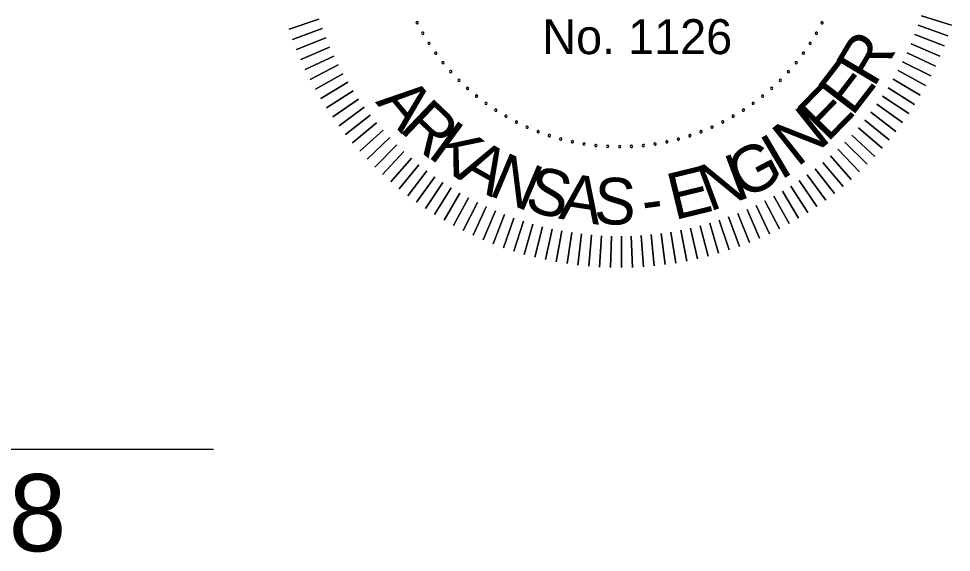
# Model space of a CAD drawing. Extents: x 164 to 3385, y 68 to 2119.
# Drawn here: x 2632.5 to 2965.9, y 339.7 to 530.6 of the extents above; entities that cross this region are included whole.
import ezdxf

# ---------------------------------------------------------------- set-up
doc = ezdxf.new("R2010")
doc.units = 0
doc.layers.add('G-ANNO-TEXT', color=7, linetype='Continuous')
doc.layers.add('R_Annotation', color=7, linetype='Continuous')

msp = doc.modelspace()

# ---------------------------------------------------------------- linework, layer by layer
at = {"layer": 'G-ANNO-TEXT'}
for points in [[(2739.82, 530.37), (2729.17, 526.84)], [(2729.17, 526.84), (2739.82, 530.37)], [(2965.87, 528.16), (2955.18, 531.57)], [(2955.18, 531.57), (2965.87, 528.16)], [(2740.99, 527.01), (2730.46, 523.15)], [(2730.46, 523.15), (2740.99, 527.01)], [(2964.62, 524.45), (2954.04, 528.19)], [(2954.04, 528.19), (2964.62, 524.45)], [(2742.27, 523.69), (2731.86, 519.5)], [(2731.86, 519.5), (2742.27, 523.69)], [(2963.26, 520.79), (2952.8, 524.86)], [(2952.8, 524.86), (2963.26, 520.79)], [(2743.65, 520.41), (2733.38, 515.89)], [(2733.38, 515.89), (2743.65, 520.41)], [(2961.79, 517.17), (2951.46, 521.57)], [(2951.46, 521.57), (2961.79, 517.17)], [(2745.13, 517.18), (2735, 512.34)], [(2735, 512.34), (2745.13, 517.18)], [(2960.2, 513.6), (2950.02, 518.32)], [(2950.02, 518.32), (2960.2, 513.6)], [(2746.71, 513.99), (2736.74, 508.84)], [(2736.74, 508.84), (2746.71, 513.99)], [(2958.5, 510.08), (2948.47, 515.11)], [(2948.47, 515.11), (2958.5, 510.08)], [(2748.4, 510.86), (2738.59, 505.39)], [(2738.59, 505.39), (2748.4, 510.86)], [(2956.69, 506.61), (2946.82, 511.96)], [(2946.82, 511.96), (2956.69, 506.61)], [(2750.18, 507.78), (2740.55, 502.01)], [(2740.55, 502.01), (2750.18, 507.78)], [(2954.77, 503.2), (2945.08, 508.86)], [(2945.08, 508.86), (2954.77, 503.2)], [(2752.05, 504.75), (2742.61, 498.69)], [(2742.61, 498.69), (2752.05, 504.75)], [(2952.74, 499.86), (2943.24, 505.82)], [(2943.24, 505.82), (2952.74, 499.86)], [(2754.02, 501.79), (2744.77, 495.43)], [(2744.77, 495.43), (2754.02, 501.79)], [(2950.62, 496.58), (2941.3, 502.84)], [(2941.3, 502.84), (2950.62, 496.58)], [(2756.08, 498.89), (2747.04, 492.25)], [(2747.04, 492.25), (2756.08, 498.89)], [(2946.06, 490.23), (2937.15, 497.06)], [(2937.15, 497.06), (2946.06, 490.23)], [(2948.39, 493.37), (2939.27, 499.91)], [(2939.27, 499.91), (2948.39, 493.37)], [(2758.23, 496.06), (2749.4, 489.13)], [(2749.4, 489.13), (2758.23, 496.06)], [(2943.63, 487.17), (2934.94, 494.27)], [(2934.94, 494.27), (2943.63, 487.17)], [(2760.47, 493.3), (2751.86, 486.1)], [(2751.86, 486.1), (2760.47, 493.3)], [(2762.8, 490.61), (2754.42, 483.14)], [(2754.42, 483.14), (2762.8, 490.61)], [(2941.11, 484.18), (2932.65, 491.55)], [(2932.65, 491.55), (2941.11, 484.18)], [(2765.21, 487.99), (2757.07, 480.26)], [(2757.07, 480.26), (2765.21, 487.99)], [(2938.49, 481.27), (2930.27, 488.91)], [(2930.27, 488.91), (2938.49, 481.27)], [(2767.69, 485.45), (2759.8, 477.47)], [(2759.8, 477.47), (2767.69, 485.45)], [(2932.99, 475.71), (2925.27, 483.85)], [(2925.27, 483.85), (2932.99, 475.71)], [(2935.79, 478.45), (2927.81, 486.34)], [(2927.81, 486.34), (2935.79, 478.45)], [(2770.26, 482.99), (2762.63, 474.76)], [(2762.63, 474.76), (2770.26, 482.99)], [(2765.53, 472.15), (2772.91, 480.61)], [(2772.91, 480.61), (2765.53, 472.15)], [(2930.12, 473.07), (2922.65, 481.44)], [(2922.65, 481.44), (2930.12, 473.07)], [(2768.52, 469.63), (2775.62, 478.31)], [(2775.62, 478.31), (2768.52, 469.63)], [(2924.12, 468.05), (2917.19, 476.88)], [(2917.19, 476.88), (2924.12, 468.05)], [(2927.16, 470.51), (2919.96, 479.12)], [(2919.96, 479.12), (2927.16, 470.51)], [(2771.58, 467.2), (2778.41, 476.11)], [(2778.41, 476.11), (2771.58, 467.2)], [(2774.72, 464.87), (2781.27, 473.99)], [(2781.27, 473.99), (2774.72, 464.87)], [(2921.01, 465.69), (2914.36, 474.73)], [(2914.36, 474.73), (2921.01, 465.69)], [(2777.93, 462.64), (2784.19, 471.96)], [(2784.19, 471.96), (2777.93, 462.64)], [(2781.21, 460.51), (2787.17, 470.02)], [(2787.17, 470.02), (2781.21, 460.51)], [(2914.57, 461.26), (2908.5, 470.7)], [(2908.5, 470.7), (2914.57, 461.26)], [(2917.82, 463.42), (2911.46, 472.67)], [(2911.46, 472.67), (2917.82, 463.42)], [(2784.56, 458.49), (2790.22, 468.18)], [(2790.22, 468.18), (2784.56, 458.49)], [(2907.86, 457.24), (2902.4, 467.04)], [(2902.4, 467.04), (2907.86, 457.24)], [(2911.25, 459.19), (2905.48, 468.82)], [(2905.48, 468.82), (2911.25, 459.19)], [(2787.96, 456.57), (2793.32, 466.43)], [(2793.32, 466.43), (2787.96, 456.57)], [(2791.43, 454.76), (2796.47, 464.79)], [(2796.47, 464.79), (2791.43, 454.76)], [(2900.92, 453.65), (2896.08, 463.78)], [(2896.08, 463.78), (2900.92, 453.65)], [(2904.42, 455.39), (2899.27, 465.36)], [(2899.27, 465.36), (2904.42, 455.39)], [(2794.95, 453.06), (2799.67, 463.24)], [(2799.67, 463.24), (2794.95, 453.06)], [(2798.52, 451.47), (2802.92, 461.8)], [(2802.92, 461.8), (2798.52, 451.47)], [(2802.14, 450), (2806.21, 460.45)], [(2806.21, 460.45), (2802.14, 450)], [(2893.76, 450.51), (2889.57, 460.92)], [(2889.57, 460.92), (2893.76, 450.51)], [(2897.36, 452.02), (2892.85, 462.3)], [(2892.85, 462.3), (2897.36, 452.02)], [(2805.81, 448.63), (2809.55, 459.21)], [(2809.55, 459.21), (2805.81, 448.63)], [(2809.51, 447.39), (2812.92, 458.08)], [(2812.92, 458.08), (2809.51, 447.39)], [(2813.25, 446.26), (2816.32, 457.05)], [(2816.32, 457.05), (2813.25, 446.26)], [(2882.69, 446.65), (2879.5, 457.41)], [(2879.5, 457.41), (2882.69, 446.65)], [(2886.42, 447.82), (2882.89, 458.47)], [(2882.89, 458.47), (2886.42, 447.82)], [(2890.11, 449.1), (2886.25, 459.64)], [(2886.25, 459.64), (2890.11, 449.1)], [(2817.03, 445.25), (2819.76, 456.13)], [(2819.76, 456.13), (2817.03, 445.25)], [(2820.84, 444.36), (2823.22, 455.32)], [(2823.22, 455.32), (2820.84, 444.36)], [(2824.67, 443.59), (2826.71, 454.62)], [(2826.71, 454.62), (2824.67, 443.59)], [(2828.52, 442.94), (2830.22, 454.03)], [(2830.22, 454.03), (2828.52, 442.94)], [(2832.4, 442.41), (2833.74, 453.55)], [(2833.74, 453.55), (2832.4, 442.41)], [(2863.59, 442.58), (2862.12, 453.71)], [(2862.12, 453.71), (2863.59, 442.58)], [(2867.46, 443.15), (2865.64, 454.23)], [(2865.64, 454.23), (2867.46, 443.15)], [(2871.3, 443.85), (2869.14, 454.86)], [(2869.14, 454.86), (2871.3, 443.85)], [(2875.13, 444.66), (2872.62, 455.6)], [(2872.62, 455.6), (2875.13, 444.66)], [(2878.92, 445.59), (2876.07, 456.45)], [(2876.07, 456.45), (2878.92, 445.59)], [(2836.28, 442), (2837.28, 453.18)], [(2837.28, 453.18), (2836.28, 442)], [(2840.18, 441.71), (2840.83, 452.92)], [(2840.83, 452.92), (2840.18, 441.71)], [(2844.09, 441.55), (2844.38, 452.77)], [(2844.38, 452.77), (2844.09, 441.55)], [(2848, 441.51), (2847.94, 452.73)], [(2847.94, 452.73), (2848, 441.51)], [(2851.91, 441.6), (2851.49, 452.81)], [(2851.49, 452.81), (2851.91, 441.6)], [(2855.81, 441.8), (2855.04, 453)], [(2855.04, 453), (2855.81, 441.8)], [(2859.71, 442.13), (2858.59, 453.3)], [(2858.59, 453.3), (2859.71, 442.13)]]:
    msp.add_lwpolyline(points, dxfattribs=at)
for centre, start, end in [((2774.94, 529.08), 117, 297), ((2774.94, 529.08), 297, 117), ((2919.67, 529.08), 63, 243), ((2919.67, 529.08), 243, 63), ((2776.97, 525.34), 120, 300), ((2776.97, 525.34), 300, 120), ((2917.64, 525.34), 60, 240), ((2917.64, 525.34), 240, 60), ((2779.19, 521.72), 123, 303), ((2779.19, 521.72), 303, 123), ((2915.42, 521.72), 57, 237), ((2915.42, 521.72), 237, 57), ((2781.6, 518.21), 126, 306), ((2781.6, 518.21), 306, 126), ((2913.01, 518.21), 54, 234), ((2913.01, 518.21), 234, 54), ((2784.19, 514.84), 129, 309), ((2784.19, 514.84), 309, 129), ((2910.42, 514.84), 51, 231), ((2910.42, 514.84), 231, 51), ((2786.95, 511.61), 132, 312), ((2786.95, 511.61), 312, 132), ((2907.66, 511.61), 48, 228), ((2907.66, 511.61), 228, 48), ((2789.88, 508.52), 135, 315), ((2789.88, 508.52), 315, 135), ((2904.73, 508.52), 45, 225), ((2904.73, 508.52), 225, 45), ((2792.96, 505.6), 138, 318), ((2792.96, 505.6), 318, 138), ((2901.65, 505.6), 42, 222), ((2901.65, 505.6), 222, 42), ((2796.19, 502.84), 141, 321), ((2796.19, 502.84), 321, 141), ((2799.57, 500.25), 144, 324), ((2799.57, 500.25), 324, 144), ((2895.04, 500.25), 36, 216), ((2895.04, 500.25), 216, 36), ((2898.42, 502.84), 39, 219), ((2898.42, 502.84), 219, 39), ((2803.07, 497.84), 147, 327), ((2803.07, 497.84), 327, 147), ((2891.54, 497.84), 33, 213), ((2891.54, 497.84), 213, 33), ((2806.7, 495.62), 150, 330), ((2806.7, 495.62), 330, 150), ((2810.43, 493.59), 153, 333), ((2810.43, 493.59), 333, 153), ((2884.18, 493.59), 27, 207), ((2884.18, 493.59), 207, 27), ((2887.91, 495.62), 30, 210), ((2887.91, 495.62), 210, 30), ((2814.27, 491.76), 156, 336), ((2814.27, 491.76), 336, 156), ((2818.2, 490.13), 159, 339), ((2818.2, 490.13), 339, 159), ((2876.41, 490.13), 21, 201), ((2876.41, 490.13), 201, 21), ((2880.34, 491.76), 24, 204), ((2880.34, 491.76), 204, 24), ((2822.21, 488.71), 162, 342), ((2822.21, 488.71), 342, 162), ((2826.28, 487.5), 165, 345), ((2826.28, 487.5), 345, 165), ((2830.42, 486.51), 348, 168), ((2864.19, 486.51), 12, 192), ((2868.32, 487.5), 15, 195), ((2868.32, 487.5), 195, 15), ((2872.4, 488.71), 18, 198), ((2872.4, 488.71), 198, 18), ((2830.42, 486.51), 168, 348), ((2834.6, 485.74), 171, 351), ((2834.6, 485.74), 351, 171), ((2838.82, 485.18), 354, 174), ((2838.82, 485.18), 174, 354), ((2843.05, 484.85), 357, 177), ((2843.05, 484.85), 177, 357), ((2847.3, 484.74), 0, 180), ((2847.3, 484.74), 180, 0), ((2851.56, 484.85), 3, 183), ((2851.56, 484.85), 183, 3), ((2855.79, 485.18), 6, 186), ((2855.79, 485.18), 186, 6), ((2860.01, 485.74), 9, 189), ((2860.01, 485.74), 189, 9), ((2864.19, 486.51), 192, 12)]:
    msp.add_arc(centre, 0.417, start, end, dxfattribs=at)
at = {"layer": 'R_Annotation'}
msp.add_lwpolyline([(2702.23, 376.43), (2352.42, 376.43), (1837.21, 673.36), (1924.62, 608.31), (1932.26, 618.58)], dxfattribs=at)

# ---------------------------------------------------------------- texts
at = {"layer": 'G-ANNO-TEXT'}
msp.add_text(' No. 1126', height=12.502, dxfattribs=at).set_placement((2815.04, 517.85))
for s, rotation, p in [('R', 59.2262, (2938.17, 505.51)), ('E', 52.4765, (2930.44, 495.25)), ('E', 45.7268, (2921.55, 485.97)), ('A', 309.5859, (2759.84, 500.69)), ('R', 316.3356, (2768.12, 490.86)), ('N', 38.4196, (2910.78, 477.18)), ('K', 323.6428, (2778.31, 481.4)), ('I', 30.5495, (2904.72, 472.58)), ('A', 330.3925, (2788.73, 473.87)), ('G', 27.7404, (2891.55, 465.59)), ('N', 337.1422, (2799.95, 467.63)), ('N', 20.4332, (2879.41, 461.38)), ('S', 344.4494, (2812.84, 462.4)), ('E', 13.6835, (2866.85, 458.44)), ('A', 351.1991, (2825.25, 459.07)), ('S', 357.9489, (2837.97, 457.22)), ('-', 7.5077, (2856.15, 457.18))]:
    msp.add_text(s, height=16.67, rotation=rotation, dxfattribs=at).set_placement(p)
at = {"layer": 'R_Annotation'}
msp.add_text('END JOB 070458', height=27.6, rotation=360, dxfattribs=at).set_placement((2356.18, 340.07))

doc.saveas('drawing.dxf')
